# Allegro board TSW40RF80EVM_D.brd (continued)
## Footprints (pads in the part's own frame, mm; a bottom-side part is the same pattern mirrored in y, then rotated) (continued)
CON_THVT_USBMINI_AB_F
  round 1.321 hole 0.813: 1(-1.6,-1.295) 2(-0.813,1.295) 3(0,-1.295) 4(0.787,1.295) 5(1.6,-1.295)
  oval 1.651x3.988 hole 0.889x2.642: MT1(-3.645,0) MT2(3.645,0)
DBV5
  rect 1.4x0.5 smd: 1(-1.1,0.95) 2(-1.1,0) 3(-1.1,-0.95) 4(1.1,-0.95) 5(1.1,0.95)
HDR_THVT_1X2_79_M
  rect 1.321x1.321 hole 0.813: 1(0,1)
  round 1.321 hole 0.813: 2(0,-1)
HDR_THVT_1X2_100_M
  rect 1.473x1.473 hole 0.965: 1(0,0)
  round 1.473 hole 0.965: 2(0,-2.54)
HDR_THVT_1X3_79_M
  rect 1.321x1.321 hole 0.813: 1(0,2)
  round 1.321 hole 0.813: 2(0,0) 3(0,-1.995)
HDR_THVT_2X5_79_M
  rect 1.321x1.321 hole 0.813: 1(-1,4)
  round 1.321 hole 0.813: 2(1,4) 3(-1,2) 4(1,2) 5(-1,0.005) 6(1,0.005) 7(-1,-1.995) 8(1,-1.995) 9(-1,-3.995) 10(1,-3.995)
HEATSINK_350X700
  rect 5.791x5.791 smd: 1(-5.715,-1.27) 2(5.715,1.27)
HEATSINK_SVT_10-1003850
  round 5.715 hole 3.175: MTG1(-3.175,18.415) MTG2(1.27,-19.685)
IND_SM_110X138
  rect 1.524x3.2 smd: 1(-1.206,0) 2(1.156,0)
IND_SM_142X189
  rect 2.007x3.505 smd: 1(-1.613,0) 2(1.613,0)
JACK_THVT_3_520X343X421
  oval 2.032x4.521 hole 1x3.5: 1(0,0)
  oval 4.013x2.032 hole 3x1: 2(-2.95,5.5) 3(-5.55,2.8)
LED_0603
  rect 0.762x0.813 smd: 1(-0.787,0) 2(0.787,0)
LED_1206
  rect 1.27x1.6 smd: 1(-1.524,0) 2(1.524,0)
LQFP_64_402X402_20
  round 1.016 smd: (-6.35,6.35) (6.35,-6.35)
  rect 2.032x0.33 smd: 1(-5.625,3.75) 2(-5.625,3.25) 3(-5.625,2.75) 4(-5.625,2.25) 5(-5.625,1.75) 6(-5.625,1.25) 7(-5.625,0.75) 8(-5.625,0.25) 9(-5.625,-0.25) 10(-5.625,-0.75) 11(-5.625,-1.25) 12(-5.625,-1.75) 13(-5.625,-2.25) 14(-5.625,-2.75) 15(-5.625,-3.25) 16(-5.625,-3.75) 33(5.625,-3.75) 34(5.625,-3.25) 35(5.625,-2.75) 36(5.625,-2.25) 37(5.625,-1.75) 38(5.625,-1.25) 39(5.625,-0.75) 40(5.625,-0.25) 41(5.625,0.25) 42(5.625,0.75) 43(5.625,1.25) 44(5.625,1.75) 45(5.625,2.25) 46(5.625,2.75) 47(5.625,3.25) 48(5.625,3.75)
  rect 0.33x2.032 smd: 17(-3.75,-5.625) 18(-3.25,-5.625) 19(-2.75,-5.625) 20(-2.25,-5.625) 21(-1.75,-5.625) 22(-1.25,-5.625) 23(-0.75,-5.625) 24(-0.25,-5.625) 25(0.25,-5.625) 26(0.75,-5.625) 27(1.25,-5.625) 28(1.75,-5.625) 29(2.25,-5.625) 30(2.75,-5.625) 31(3.25,-5.625) 32(3.75,-5.625) 49(3.75,5.625) 50(3.25,5.625) 51(2.75,5.625) 52(2.25,5.625) 53(1.75,5.625) 54(1.25,5.625) 55(0.75,5.625) 56(0.25,5.625) 57(-0.25,5.625) 58(-0.75,5.625) 59(-1.25,5.625) 60(-1.75,5.625) 61(-2.25,5.625) 62(-2.75,5.625) 63(-3.25,5.625) 64(-3.75,5.625)
MFG125_PLATED
  round 3.556 hole 3.175: 1(0,0)
MSOP_8_118X118_26
  rect 1.575x0.406 smd: 1(-2.225,0.975) 2(-2.225,0.325) 3(-2.225,-0.325) 4(-2.225,-0.975) 5(2.225,-0.975) 6(2.225,-0.325) 7(2.225,0.325) 8(2.225,0.975)
PDFN_6_P35MM
  custom 0.045x0.045 smd: 1(-0.5,0.35) 2(-0.5,0) 3(-0.5,-0.35) 4(0.5,-0.35) 5(0.5,0) 6(0.5,0.35)
PROBE_POINT_22PAD
  round 0.508 smd: 1(0,0)
PROBE_POINT_30PAD
  round 0.762 smd: 1(0,0)
QFN20_RGR_P5MM
  custom 0.076x0.076 smd: 1(-1.85,1) 2(-1.85,0.5) 3(-1.85,0) 4(-1.85,-0.5) 5(-1.85,-1) 6(-1,-1.85) 7(-0.5,-1.85) 8(0,-1.85) 9(0.5,-1.85) 10(1,-1.85) 11(1.85,-1) 12(1.85,-0.5) 13(1.85,0) 14(1.85,0.5) 15(1.85,1) 16(1,1.85) 17(0.5,1.85) 18(0,1.85) 19(-0.5,1.85) 20(-1,1.85)
  rect 2.032x2.032 smd: 21(0,0)
QFN40_RTA_RTB_RHA
  custom 0.076x0.076 smd: 1(-3.025,2.25) 2(-3.025,1.75) 3(-3.025,1.25) 4(-3.025,0.75) 5(-3.025,0.25) 6(-3.025,-0.25) 7(-3.025,-0.75) 8(-3.025,-1.25) 9(-3.025,-1.75) 10(-3.025,-2.25) 11(-2.25,-3.025) 12(-1.75,-3.025) 13(-1.25,-3.025) 14(-0.75,-3.025) 15(-0.25,-3.025) 16(0.25,-3.025) 17(0.75,-3.025) 18(1.25,-3.025) 19(1.75,-3.025) 20(2.25,-3.025) 21(3.025,-2.25) 22(3.025,-1.75) 23(3.025,-1.25) 24(3.025,-0.75) 25(3.025,-0.25) 26(3.025,0.25) 27(3.025,0.75) 28(3.025,1.25) 29(3.025,1.75) 30(3.025,2.25) 31(2.25,3.025) 32(1.75,3.025) 33(1.25,3.025) 34(0.75,3.025) 35(0.25,3.025) 36(-0.25,3.025) 37(-0.75,3.025) 38(-1.25,3.025) 39(-1.75,3.025) 40(-2.25,3.025)
  rect 4.572x4.572 smd: 41(0,0)
QFN_20_183X144_RGY
  rect 0.762x0.356 smd: 1(-2.125,-0.75) 10(2.125,-0.75) 11(2.125,0.75) 20(-2.125,0.75)
  rect 0.356x0.762 smd: 2(-1.75,-1.625) 3(-1.25,-1.625) 4(-0.75,-1.625) 5(-0.25,-1.625) 6(0.25,-1.625) 7(0.75,-1.625) 8(1.25,-1.625) 9(1.75,-1.625) 12(1.75,1.625) 13(1.25,1.625) 14(0.75,1.625) 15(0.25,1.625) 16(-0.25,1.625) 17(-0.75,1.625) 18(-1.25,1.625) 19(-1.75,1.625)
  rect 3.15x2.159 smd: 21(0,0)
QFN_20_199X199_0P65MM
  rect 0.991x0.356 smd: 1(-2.4,1.3) 2(-2.4,0.65) 3(-2.4,0) 4(-2.4,-0.65) 5(-2.4,-1.3) 11(2.4,-1.3) 12(2.4,-0.65) 13(2.4,0) 14(2.4,0.65) 15(2.4,1.3)
  rect 0.356x0.991 smd: 6(-1.3,-2.4) 7(-0.65,-2.4) 8(0,-2.4) 9(0.65,-2.4) 10(1.3,-2.4) 16(1.3,2.4) 17(0.65,2.4) 18(0,2.4) 19(-0.65,2.4) 20(-1.3,2.4)
  rect 3.15x3.15 smd: 21(0,0)
QFN_64_360X360_0P50MM_PWRPAD
  oval 1.016x0.305 smd: 1(-4.58,3.753) 2(-4.58,3.252) 3(-4.58,2.752) 4(-4.58,2.252) 5(-4.58,1.751) 6(-4.58,1.251) 7(-4.58,0.751) 8(-4.58,0.25) 9(-4.58,-0.25) 10(-4.58,-0.751) 11(-4.58,-1.251) 12(-4.58,-1.751) 13(-4.58,-2.252) 14(-4.58,-2.752) 15(-4.58,-3.252) 16(-4.58,-3.753) 33(4.58,-3.753) 34(4.58,-3.252) 35(4.58,-2.752) 36(4.58,-2.252) 37(4.58,-1.751) 38(4.58,-1.251) 39(4.58,-0.751) 40(4.58,-0.25) 41(4.58,0.25) 42(4.58,0.751) 43(4.58,1.251) 44(4.58,1.751) 45(4.58,2.252) 46(4.58,2.752) 47(4.58,3.252) 48(4.58,3.753)
  oval 0.305x1.016 smd: 17(-3.753,-4.58) 18(-3.252,-4.58) 19(-2.752,-4.58) 20(-2.252,-4.58) 21(-1.751,-4.58) 22(-1.251,-4.58) 23(-0.751,-4.58) 24(-0.25,-4.58) 25(0.25,-4.58) 26(0.751,-4.58) 27(1.251,-4.58) 28(1.751,-4.58) 29(2.252,-4.58) 30(2.752,-4.58) 31(3.252,-4.58) 32(3.753,-4.58) 49(3.753,4.58) 50(3.252,4.58) 51(2.752,4.58) 52(2.252,4.58) 53(1.751,4.58) 54(1.251,4.58) 55(0.751,4.58) 56(0.25,4.58) 57(-0.25,4.58) 58(-0.751,4.58) 59(-1.251,4.58) 60(-1.751,4.58) 61(-2.252,4.58) 62(-2.752,4.58) 63(-3.252,4.58) 64(-3.753,4.58)
  rect 7.366x7.366 smd: 65(0,0)
QFN_72_10MMX10MM_0P50MM_PWRPAD
  oval 0.6x0.24 smd: 1(-4.9,4.25) 2(-4.9,3.75) 3(-4.9,3.25) 4(-4.9,2.75) 5(-4.9,2.25) 6(-4.9,1.75) 7(-4.9,1.25) 8(-4.9,0.75) 9(-4.9,0.25) 10(-4.9,-0.25) 11(-4.9,-0.75) 12(-4.9,-1.25) 13(-4.9,-1.75) 14(-4.9,-2.25) 15(-4.9,-2.75) 16(-4.9,-3.25) 17(-4.9,-3.75) 18(-4.9,-4.25) 37(4.9,-4.25) 38(4.9,-3.75) 39(4.9,-3.25) 40(4.9,-2.75) 41(4.9,-2.25) 42(4.9,-1.75) 43(4.9,-1.25) 44(4.9,-0.75) 45(4.9,-0.25) 46(4.9,0.25) 47(4.9,0.75) 48(4.9,1.25) 49(4.9,1.75) 50(4.9,2.25) 51(4.9,2.75) 52(4.9,3.25) 53(4.9,3.75) 54(4.9,4.25)
  oval 0.24x0.6 smd: 19(-4.25,-4.9) 20(-3.75,-4.9) 21(-3.25,-4.9) 22(-2.75,-4.9) 23(-2.25,-4.9) 24(-1.75,-4.9) 25(-1.25,-4.9) 26(-0.75,-4.9) 27(-0.25,-4.9) 28(0.25,-4.9) 29(0.75,-4.9) 30(1.25,-4.9) 31(1.75,-4.9) 32(2.25,-4.9) 33(2.75,-4.9) 34(3.25,-4.9) 35(3.75,-4.9) 36(4.25,-4.9) 55(4.25,4.9) 56(3.75,4.9) 57(3.25,4.9) 58(2.75,4.9) 59(2.25,4.9) 60(1.75,4.9) 61(1.25,4.9) 62(0.75,4.9) 63(0.25,4.9) 64(-0.25,4.9) 65(-0.75,4.9) 66(-1.25,4.9) 67(-1.75,4.9) 68(-2.25,4.9) 69(-2.75,4.9) 70(-3.25,4.9) 71(-3.75,4.9) 72(-4.25,4.9)
  rect 8.382x8.382 smd: 73(0,0)
SMA_SMEL_DUAL_PSF-S01_250X215
  rect 0.508x4.064 smd: 1(0,-2.032)
  rect 3.048x4.064 smd: 2(-3.556,-2.032) 3(3.556,-2.032) 4(-3.556,-2.032) 5(3.556,-2.032)
SMA_THVT_312X312
  round 2.337 hole 1.575: 1(0,0)
  round 2.464 hole 1.702: 2(-2.54,2.54) 3(2.54,2.54) 4(2.54,-2.54) 5(-2.54,-2.54)
SMP_B120
  rect 0.508x1.321 smd: 1(0,-3.1)
  custom 1.3x1.3 smd: 2(0,0)
SON_DSG_8
  rect 0.508x0.33 smd: 1(-0.903,0.75) 2(-0.903,0.25) 3(-0.903,-0.25) 4(-0.903,-0.75) 5(0.903,-0.75) 6(0.903,-0.25) 7(0.903,0.25) 8(0.903,0.75)
  rect 0.762x1.778 smd: 9(0,0)
SON_Q5B_8
  rect 1.372x0.711 smd: 1(-2.767,1.905) 2(-2.767,0.635) 3(-2.767,-0.635) 4(-2.767,-1.905) 5(2.767,-1.905) 6(2.767,-0.635) 7(2.767,0.635) 8(2.767,1.905)
SOT_416_3_63X31
  rect 0.508x0.356 smd: 1(0,-0.152) 2(0,-1.168) 3(1.295,-0.66)
SW_SMVT_SPST_EVQPJX_2
  rect 2.007x1.6 smd: 1(-2.7,0) 2(2.7,0)
TESTPOINT_62DIA
  round 2.337 hole 1.575: 1(0,0)
TFMR_5_150X150_50
  rect 1.651x0.762 smd: 1(1.587,1.27) 2(1.587,0) 3(1.587,-1.27) 4(-1.587,-1.27) 6(-1.587,1.27)
TP_THVT_060_RND
  round 1.575 hole 1.016: 1(0,0)
USIL_8_3MMX2P8MM_0P65MM
  rect 0.5x0.4 smd: 1(-1.1,0.975) 2(-1.1,0.325) 3(-1.1,-0.325) 4(-1.1,-0.975) 5(1.1,-0.975) 6(1.1,-0.325) 7(1.1,0.325) 8(1.1,0.975)
  rect 1.1x1.9 smd: 9(0,0)
VCXO_6_CUSTOM
  rect 5.74x1.956 smd: 1(-3.81,2.54) 2(-3.81,0) 3(-3.81,-2.54) 4(3.81,-2.54) 5(3.81,0) 6(3.81,2.54)
XTAL_4_SM_130X102
  rect 1.4x1.2 smd: 1(-1.1,-0.85) 2(1.1,-0.85) 3(1.1,0.85) 4(-1.1,0.85)

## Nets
1.8V_USB: C246.2 C250.2 C253.2 C262.1 C263.1 C265.2 C439.2 R327.1 U10.12(VCORE#12) U10.37(VCORE#37) U10.49(VREGOUT) U10.64(VCORE#64) U11.2(VCCA) U11.10(OE) U32.2(VCCA) U32.10(OE)
3.3V_USB: C245.2 C249.2 C251.2 C255.2 C259.1 C264.1 C268.2 C438.1 FB12.1 FB13.3 FB14.1 R155.2 R156.2 R157.2 R326.1 U10.20(VCCIO#20) U10.31(VCCIO#31) U10.42(VCCIO#42) U10.50(VREGIN) U10.56(VCCIO#56) U11.19(VCCB) U12.6(ORG) U12.8(VCC) U32.19(VCCB)
5.0V_SOURCE: F1.1 J17.1 Q4.5(D5) Q4.6(D6) Q4.7(D7) Q4.8(D8) TP10.1(TP) U14.5(VIN)
5VUSB: R138.2 R146.1
+1.8V_ANA: C71.1 C72.2 C73.1 C74.1 C75.1 C76.2 C77.1 C78.1 C302.1 C303.1 FB49.2 PP8.1 R363.2 U1.G11(VDDA18#G11) U1.G12(VDDOUT18#G12) U1.H11(VDDA18#H11) U1.H12(VDDOUT18#H12)
+1.8V_CLK: C79.1 C80.2 C81.1 C82.1 C101.1 C102.2 C103.1 C297.1 C298.1 FB47.2 PP5.1 U1.B7(VDDTX18) U1.B9(VDDAPLL18#B9) U1.B10(VDDAPLL18#B10)
+1.8V_DIG: C89.1 C90.2 C91.1 C92.1 C93.1 C94.2 C96.1 C97.1 C98.2 C99.1 C100.1 C300.1 C301.1 FB48.2 JP1.1(PIN1) JP2.1(PIN1) PP7.1 R30.1 U1.B3(VDDS18#B3) U1.B4(VDDS18#B4) U1.H2(VDDR18#H2) U1.H5(VDDIO18) U1.J2(VDDR18#J2)
+1.8V_VDDVCO: C83.1 C84.2 C85.1 C86.1 C443.1 C444.1 L17.1 PP52.1 U1.D9(VDDAVCO18#D9) U1.E9(VDDAVCO18#E9)
+3.3V: C426.2 FB38.1 FB39.1 R219.1 R225.1 U23.8(VOUT)
+3.3V_LMX: C172.1 C173.1 C174.2 C176.1 C179.1 C180.2 C185.1 C187.2 C353.1 C354.1 C355.1 C356.1 FB38.2 PP23.1 R60.2 U5.7(VCCDIG) U5.11(VCCCP) U5.15(VCCDIV) U5.21(VCCBUF) U5.26(VCCDBLR) U5.37(VCCVCO)
+3.3V_LMXRF: C139.1 C168.1 C178.1 C358.1 C359.1 C423.1 C424.1 FB39.2 R38.1 R39.1 R58.2 R59.2 R61.2 R62.2 R213.1 R214.1 R215.1 R216.1
+3.3VCLK: C346.1 C347.1 FB2.1 FB3.1 FB4.1 FB5.1 FB6.1 FB10.1 FB11.1 FB37.3 JP6.2 PP22.1 R73.1 R104.1 R112.1 R359.1 U22.3(SENSE)
+5VIN: C252.1 C275.1 C276.1 C277.2 C327.2 D6.1(ANODE) D7.1(ANODE) FB16.1 FB21.1 FB22.1 FB23.1 J38.1 L13.1 L15.1 L16.1 R136.2 U8.1(VIN) U21.12(BIAS)
+5VIN_ADC: C435.1 C436.2 C437.1 FB25.1 FB26.1 FB27.1 FB44.1 L10.1 L11.1 L12.1 R332.1
+5VIN_CLK: C340.1 C341.2 C342.2 C425.1 C440.1 C441.2 C442.1 FB45.1 R340.2 R342.2 U22.15(IN2) U22.16(IN1) U23.3(VIN1) U23.4(VIN2)
-1.8V: C279.1 FB17.1 U15.4(VOUT)
-1.8V_VEE: C104.1 C105.2 C106.1 C107.1 C108.1 C109.1 C278.1 C280.1 PP1.1 R161.2 R236.1 U1.D10(VEEB_-1.8V#D10) U1.E10(VEEB_-1.8V#E10) U1.K10(VEEA_-1.8V#K10) U1.L10(VEEA_-1.8V#L10)
AVDD1.9V: C142.1 C143.1 C144.1 C145.1 C146.1 C147.1 C362.1 C364.1 PP31.1 R356.1 U2.10(AVDD19#10) U2.16(AVDD19#16) U2.24(AVDD19#24) U2.31(AVDD19#31) U2.39(AVDD19#39) U2.45(AVDD19#45)
AVDD1.15V: C112.1 C113.1 C114.1 C115.1 C116.1 C117.1 C118.1 C119.1 C120.1 C121.1 C122.1 C381.1 C382.1 PP32.1 R357.1 U2.9(AVDD#9) U2.12(AVDD#12) U2.15(AVDD#15) U2.17(AVDD#17) U2.25(AVDD#25) U2.30(AVDD#30) U2.38(AVDD#38) U2.40(AVDD#40) U2.43(AVDD#43) U2.44(AVDD#44) U2.46(AVDD#46)
DVDD1.15V: C128.1 C129.1 C130.1 C131.1 C132.1 C133.1 C134.1 C261.1 C377.1 C378.1 JP4.1(PIN1) PP33.1 R47.2 R358.1 U2.4(DVDD#4) U2.8(DVDD#8) U2.47(DVDD#47) U2.51(DVDD#51) U2.57(DVDD#57) U2.64(DVDD#64) U2.70(DVDD#70) U31.2(VCCA) U31.10(OE)
DVDD_1P0V: C30.1 C31.2 C32.1 C33.1 C34.1 C35.1 C36.1 C37.1 C38.1 C39.1 C40.1 C41.1 C42.1 C288.1 C289.1 PP3.1 R168.2 R237.1 R360.2 U1.A5(VDD_1V#A5) U1.B5(VDD_1V#B5) U1.C5(VDD_1V#C5) U1.D5(VDD_1V#D5) U1.D7(VDD_1V#D7) U1.E3(VDD_1V#E3) U1.E4(VDD_1V#E4) U1.E5(VDD_1V#E5) U1.E6(VDD_1V#E6) U1.F4(VDD_1V#F4) U1.F5(VDD_1V#F5) U1.G4(VDD_1V#G4) U1.G5(VDD_1V#G5)
GND: C28.2 C29.2 C30.2 C31.1 C32.2 C33.2 C34.2 C35.2 C36.2 C37.2 C38.2 C39.2 C40.2 C41.2 C42.2 C43.2 C44.1 C45.2 C46.2 C47.2 C48.1 C49.2 C50.2 C51.2 C52.1 C53.2 C54.2 C55.2 C56.1 C57.2 C58.2 C59.2 C60.1 C61.2 C62.2 C63.2 C64.1 C65.2 C66.2 C67.2 C68.1 C69.2 C70.2 C71.2 C72.1 C73.2 C74.2 C75.2 C76.1 C77.2 C78.2 C79.2 C80.1 C81.2 C82.2 C83.2 C84.1 C85.2 C86.2 C87.1 C88.2 C89.2 C90.1 C91.2 C92.2 C93.2 C94.1 C95.2 C96.2 C97.2 C98.1 C99.2 C100.2 C101.2 C102.1 C103.2 C104.2 C105.1 C106.2 C107.2 C108.2 C109.2 C112.2 C113.2 C114.2 C115.2 C116.2 C117.2 C118.2 C119.2 C120.2 C121.2 C122.2 C128.2 C129.2 C130.2 C131.2 C132.2 C133.2 C134.2 C139.2 C142.2 C143.2 C144.2 C145.2 C146.2 C147.2 C154.2 C157.2 C159.1 C161.1 C165.1 C166.1 C168.2 C172.2 C173.2 C174.1 C176.2 C177.1 C178.2 C179.2 C180.1 C182.2 C183.1 C185.2 C186.1 C187.1 C188.1 C189.1 C190.1 C191.1 C192.2 C194.2 C195.2 C200.2 C203.2 C206.1 C218.1 C219.1 C222.1 C223.1 C225.1 C229.1 C232.1 C233.1 C234.1 C235.1 C236.1 C237.1 C238.1 C239.1 C240.1 C241.2 C242.2 C243.1 C244.1 C245.1 C246.1 C247.2 C248.2 C249.1 C250.1 C251.1 C252.2 C253.1 C254.2 C255.1 C256.2 C257.2 C258.2 C259.2 C260.1 C261.2 C262.2 C263.2 C264.2 C265.1 C266.2 C267.2 C268.1 C269.2 C270.2 C273.2 C274.1 C275.2 C276.2 C277.1 C278.2 C279.2 C280.2 C281.2 C283.2 C285.2 C288.2 C289.2 C290.1 C294.1 C295.2 C297.2 C298.2 C299.2 C300.2 C301.2 C302.2 C303.2 C308.2 C309.2 C313.1 C314.2 C315.2 C316.2 C318.2 C320.2 C324.2 C325.2 C326.1 C327.1 C340.2 C341.1 C342.1 C343.2 C344.2 C345.2 C346.2 C347.2 C348.2 C353.2 C354.2 C355.2 C356.2 C358.2 C359.2 C362.2 C364.2 C365.2 C366.1 C367.2 C376.1 C377.2 C378.2 C379.2 C380.1 C381.2 C382.2 C423.2 C424.2 C425.2 C426.1 C435.2 C436.1 C437.2 C438.2 C439.1 C440.2 C441.1 C442.2 C443.2 C444.2 C445.1 C446.1 C447.1 C448.1 D1.2(CATHODE) D2.2(CATHODE) D3.2(CATHODE) D4.2(CATHODE) D5.2(CATHODE) D9.2(CATHODE) D10.2(CATHODE) FB13.2 FB17.2 FB18.2 FB20.2 FB37.2 FB40.2 FB41.2 FB42.2 FB53.2 HS1.MTG1 HS1.MTG2 HS2.1 HS2.2 J1.2(GND#2) J1.3(GND#3) J1.4(GND#4) J1.5(GND#5) J3.2(GND#2) J3.3(GND#3) J3.4(GND#4) J3.5(GND#5) J4.2(GND#2) J4.3(GND#3) J4.4(GND#4) J4.5(GND#5) J8.2(SHIELD1) J9.2(SHIELD2) J9.3(SHIELD3) J9.4(SHIELD4) J9.5(SHIELD1) J10.2(SHIELD2) J10.3(SHIELD3) J10.4(SHIELD4) J10.5(SHIELD1) J12.2(GND#2) J12.3(GND#3) J12.4(GND#4) J12.5(GND#5) J13.2(SHIELD1) J14.A1 J14.A4 J14.A5 J14.A8 J14.A9 J14.A12 J14.A13 J14.A16 J14.A17 J14.A20 J14.A21 J14.A24 J14.A25 J14.A28 J14.A29 J14.A32 J14.A33 J14.A36 J14.A37 J14.A40 J14.B2 J14.B3 J14.B6 J14.B7 J14.B10 J14.B11 J14.B14 J14.B15 J14.B18 J14.B19 J14.B22 J14.B23 J14.B26 J14.B27 J14.B30 J14.B31 J14.B34 J14.B35 J14.B38 J14.B39 J14.C1 J14.C4 J14.C5 J14.C8 J14.C9 J14.C12 J14.C13 J14.C16 J14.C17 J14.C20 J14.C21 J14.C24 J14.C25 J14.C28 J14.C29 J14.C32 J14.C33 J14.C36 J14.C38 J14.C40 J14.D2 J14.D3 J14.D6 J14.D7 J14.D10 J14.D13 J14.D16 J14.D19 J14.D22 J14.D25 J14.D28 J14.D37 J14.D39 J14.E1 J14.E4 J14.E5 J14.E8 J14.E11 J14.E14 J14.E17 J14.E20 J14.E23 J14.E26 J14.E29 J14.E32 J14.E35 J14.E38 J14.E40 J14.F3 J14.F6 J14.F9 J14.F12 J14.F15 J14.F18 J14.F21 J14.F24 J14.F27 J14.F30 J14.F33 J14.F36 J14.F39 J14.G1 J14.G4 J14.G5 J14.G8 J14.G11 J14.G14 J14.G17 J14.G20 J14.G23 J14.G26 J14.G29 J14.G32 J14.G35 J14.G38 J14.G40 J14.H3 J14.H6 J14.H9 J14.H12 J14.H15 J14.H18 J14.H21 J14.H24 J14.H27 J14.H30 J14.H33 J14.H36 J14.H39 J14.J1 J14.J4 J14.J5 J14.J8 J14.J11 J14.J14 J14.J17 J14.J20 J14.J23 J14.J26 J14.J29 J14.J32 J14.J35 J14.J38 J14.J40 J14.K2 J14.K3 J14.K6 J14.K9 J14.K12 J14.K15 J14.K18 J14.K21 J14.K24 J14.K27 J14.K30 J14.K33 J14.K36 J14.K39 J15.5(GND) J15.MT1(SHLD#MT1) J15.MT2(SHLD#MT2) J17.2 J17.3 J38.2 JP1.3(PIN3) JP2.3(PIN3) JP3.2(PIN2) JP4.3(PIN3) JP5.1 JP7.2(PIN2) JP8.2(PIN2) MT1.1 MT2.1 MT3.1 Q1.2(E) Q2.2(E) R2.2 R3.2 R21.2 R22.2 R24.2 R25.2 R31.2 R49.1 R50.1 R67.1 R70.2 R71.2 R72.2 R76.2 R77.2 R78.2 R79.2 R80.2 R81.1 R82.1 R87.2 R89.2 R90.2 R93.2 R94.2 R95.2 R100.2 R101.2 R102.2 R103.2 R105.2 R106.2 R108.2 R109.2 R110.2 R111.2 R114.2 R116.2 R117.2 R119.2 R120.2 R121.2 R122.1 R147.2 R151.1 R163.2 R169.2 R173.2 R182.1 R188.1 R189.1 R190.1 R200.2 R203.2 R206.2 R208.2 R210.2 R212.2 R218.2 R220.2 R239.2 R256.2 R331.1 R334.1 R335.1 R337.2 R339.2 R341.2 R343.2 R354.2 SW1.1 T3.4(PRI) TP1.1(TP) TP2.1(TP) TP6.1(TP) TP7.1(TP) TP8.1(TP) TP9.1(TP) TP11.1(TP) TP14.1(TP) U1.A2(DGND#A2) U1.A8(VSSCLK#A8) U1.A11(VSSCLK#A11) U1.B2(DGND#B2) U1.B8(VSSCLK#B8) U1.B11(VSSCLK#B11) U1.B12(VSSCLK#B12) U1.C2(DGND#C2) U1.C11(AGNDB#C11) U1.C12(AGNDB#C12) U1.D2(DGND#D2) U1.D6(DGND#D6) U1.D11(AGNDB#D11) U1.D12(VOUTBP) U1.E2(DGND#E2) U1.E7(DGND#E7) U1.E11(AGNDB#E11) U1.F2(DGND#F2) U1.F6(DGND#F6) U1.F8(VSSCLK#F8) U1.F9(VSSCLK#F9) U1.F10(VSSCLK#F10) U1.F12(AGNDB#F12) U1.G2(DGND#G2) U1.G7(DGND#G7) U1.H6(DGND#H6) U1.J7(DGND#J7) U1.J8(VSSCLK#J8) U1.J9(VSSCLK#J9) U1.J10(VSSCLK#J10) U1.J12(AGNDA#J12) U1.K2(DGND#K2) U1.K11(AGNDA#K11) U1.L2(DGND#L2) U1.L3(DGND#L3) U1.L4(DGND#L4) U1.L5(DGND#L5) U1.L11(AGNDA#L11) U1.L12(VOUTAP) U1.M6(DGND#M6) U1.M11(AGNDA#M11) U1.M12(AGNDA#M12) U2.3(DGND#3) U2.18(AGND#18) U2.23(AGND#23) U2.26(AGND#26) U2.29(AGND#29) U2.32(AGND#32) U2.37(AGND#37) U2.52(DGND#52) U2.60(DGND#60) U2.67(DGND#67) U2.73(THERMALPAD) U3.2(GND) U4.2(GND) U5.2(GND#2) U5.4(GND#4) U5.6(GND#6) U5.13(GND#13) U5.14(GND#14) U5.25(GND#25) U5.31(GND#31) U5.34(GND#34) U5.39(GND#39) U5.40(GND#40) U5.41(PWRPAD) U7.65(DAP) U8.2(GND) U10.1(GND#1) U10.5(GND#5) U10.10(AGND) U10.11(GND#11) U10.13(TEST) U10.15(GND#15) U10.25(GND#25) U10.35(GND#35) U10.47(GND#47) U10.51(GND#51) U11.11(GND) U11.21(PWRPAD) U12.5(GND) U14.2(GND) U15.2(GND) U15.9(PAD) U17.5(GND#5) U17.6(GND#6) U17.9(PWRPAD) U19.5(GND#5) U19.6(GND#6) U19.9(PWRPAD) U21.8(GND#8) U21.18(GND#18) U21.21(THERMPAD) U22.7(GND) U22.8(1P6V) U22.21(PWRPAD) U23.5(GND#5) U23.6(GND#6) U23.9(PWRPAD) U24.5(GND#5) U24.6(GND#6) U24.9(PWRPAD) U25.5(GND#5) U25.6(GND#6) U25.9(PWRPAD) U26.5(GND#5) U26.6(GND#6) U26.9(PWRPAD) U27.2(GND) U28.2(GND) U29.2(GND) U30.2(GND) U31.11(GND) U31.21(PWRPAD) U32.11(GND) U32.21(PWRPAD) Y1.3(GND) Y2.2 Y2.4
V1: JP3.1(PIN1) R38.2 U29.1(V1) U30.1(V1)
V2: JP3.3(PIN3) R39.2 U29.5(V2) U30.5(V2)
V3: JP7.1(PIN1) R214.2 U27.1(V1) U28.1(V1)
V4: JP7.3(PIN3) R213.2 U27.5(V2) U28.5(V2)
V5: JP8.1(PIN1) R216.2 U3.1(V1) U4.1(V1)
V6: JP8.3(PIN3) R215.2 U3.5(V2) U4.5(V2)
1P0V: FB50.1 FB51.1 FB52.1 R176.1
1P8V: C295.1 FB24.2 FB47.1 FB48.1 FB49.1 L14.2 L17.2 R238.1
3P3VAUX: J14.D32 PP51.1
+1P0V_ANA: C67.1 C68.2 C69.1 C70.1 C324.1 C325.1 FB52.2 PP15.1 R365.2 U1.F11(VDDAB_1V) U1.J11(VDDAA_1V)
+1P0V_CLK: C51.1 C52.2 C53.1 C54.1 C55.1 C56.2 C57.1 C58.1 C63.1 C64.2 C65.1 C66.1 C87.2 C88.1 C95.1 C308.1 C309.1 FB50.2 PP11.1 U1.B6(VDDTX) U1.D8(VDDPLL_1V#D8) U1.E8(VDDPLL_1V#E8) U1.G9(VDDCLK_1V#G9) U1.G10(VDDL2B_1V) U1.H9(VDDCLK_1V#H9) U1.H10(VDDL2A_1V)
+1P0V_DIG: C43.1 C44.2 C45.1 C46.1 C314.1 C316.1 FB51.2 PP13.1 R361.1 U1.F7(VDDE_1V#F7) U1.G6(VDDE_1V#G6) U1.H7(VDDE_1V#H7) U1.J6(VDDE_1V#J6)
+1P0V_VDDL1: C47.1 C48.2 C49.1 C50.1 C59.1 C60.2 C61.1 C62.1 R360.1 R361.2 U1.G8(VDDL1B_1V) U1.H3(VDDT_1V#H3) U1.H8(VDDL1A_1V) U1.J3(VDDT_1V#J3)
A_IN: C160.1 J9.1(CENTER)
ADC_CLK: C153.1 J8.1(CENTER)
ADC_CLKINM: C428.2 R229.1 U2.28(CLKINM)
ADC_CLKINP: C427.2 R229.2 U2.27(CLKINP)
ADC_LKXEN: C434.1 U28.6(RFC)
ADC_LKXEP: C433.1 U27.6(RFC)
ADC_LXEN: C432.1 U30.6(RFC)
ADC_LXEP: C431.1 U29.6(RFC)
ADC_RESET: R49.2 SW2.2 U2.48(RESET) U31.6(A5)
ADC_SCLK: U2.6(SCLK) U31.1(A1)
ADC_SDIO: U2.5(SDATA) U31.3(A2)
ADC_SDO: U2.11(SDOUT) U31.4(A3)
ADC_SEN: U2.7(SEN) U31.5(A4)
ADC_SYNC_N: J14.G13 U2.36(SYNCBM)
ADC_SYNC_P: J14.G12 U2.35(SYNCBP)
ADC_SYSREFN: R45.1 R99.2 R102.1 U2.34(SYSREFM)
ADC_SYSREFP: R45.2 R96.2 R103.1 U2.33(SYSREFP)
AIN+: C162.1 R55.2 T4.3(SEC) T5.1(SEC DOT)
AIN-: C158.1 R54.2 T4.1(SEC DOT) T5.3(SEC)
AINM: C158.2 T5.4(PRI) U2.41(INAM)
AINP: C162.2 T5.6(PRI DOT) U2.42(INAP)
ALARM: TP3.1(TP) U1.K8(ALARM)
ATEST: TP15.1(TP) U1.C8(ATEST)
B_IN: C164.1 J10.1(CENTER)
BIN+: C163.1 R56.2 T6.1(SEC DOT) T7.3(SEC)
BIN-: C167.1 R57.2 T6.3(SEC) T7.1(SEC DOT)
BINM: C167.2 T7.6(PRI DOT) U2.14(INBM)
BINP: C163.2 T7.4(PRI) U2.13(INBP)
CAR_SYSREF_M: R86.1 R89.1 U7.4(SDCLKOUT1N)
CAR_SYSREF_P: R85.1 R90.1 U7.3(SDCLKOUT1P)
CAR_SYSREFM: J14.G10 R86.2
CAR_SYSREFP: J14.G9 R85.2
CE: JP5.2 R60.1 U5.1(CE)
CLK_LAO_0M: J14.G7 R118.2
CLK_LAO_0P: J14.G6 R115.2
CLKIN0_N: C206.2 U7.38(CLKIN0N)
CLKIN0_P: C204.2 U7.37(CLKIN0P)
CLKIN1N: C384.2 R234.1 U7.35(CLKIN1N/FBCLKINN/FINN)
CLKIN1P: C383.2 R234.2 U7.34(CLKIN1P/FBCLKINP/FINP)
CLKLA_0M: R118.1 R119.1 U7.63(DCLKOUT12N)
CLKLA_0P: R115.1 R117.1 U7.62(DCLKOUT12P)
CP1: C198.1 C200.1 R73.2 U7.32(CPOUT1) Y1.1(VC)
CP2: C202.1 C203.1 U7.46(CPOUT2)
CPOUT: C192.1 C193.1 R68.1 U5.12(CPOUT)
DA0N: C111.2 J14.B13
DA0P: C110.2 J14.B12
DA1N: C124.2 J14.A15
DA1P: C123.2 J14.A14
DA2N: C126.2 J14.B17
DA2P: C125.2 J14.B16
DA3N: C135.2 J14.A19
DA3P: C127.2 J14.A18
DAC_ALT_SYNC_N: J14.F20 U1.C6(SYNC1BN)
DAC_ALT_SYNC_P: J14.F19 U1.C7(SYNC1BP)
DAC_CLKOUTN: C9.2 U4.4(RF2)
DAC_CLKOUTP: C7.2 U3.4(RF2)
DAC_RESET: C28.1 R30.2 R148.1 R329.2 SW1.2 U1.K9(RESETB)
DAC_SCLK: R232.1 R304.1 R309.1
DAC_SDENB: R231.1 R307.1 R311.1
DAC_SDIO: R230.1 R305.1 R310.1
DAC_SDO: R233.1 R306.1 R308.1
DAC_SYNC_N: J14.F11 U1.C3(SYNC0BN)
DAC_SYNC_P: J14.F10 U1.C4(SYNC0BP)
DACCLK_IN: C1.1 J1.1(CENTER)
DACCLK_N: C361.1 U1.A9(DACCLKN)
DACCLK_P: C360.1 U1.A10(DACCLKP)
DACCLK_SE: C1.2 R1.2 R2.1
DACCLKSE: R1.1 R3.1 U1.A12(DACCLKSE)
DB0N: C137.2 J14.A11
DB0P: C136.2 J14.A10
DB1N: C140.2 J14.C7
DB1P: C138.2 J14.C6
DB2N: C148.2 J14.A7
DB2P: C141.2 J14.A6
DB3N: C150.2 J14.A3
DB3P: C149.2 J14.A2
DCLKOUT2N: C197.1 R72.1 U7.16(DCLKOUT2N)
DCLKOUT2P: C196.1 R71.1 U7.15(DCLKOUT2P)
DCLKOUT4N: C208.1 R95.1 U7.25(DCLKOUT4N)
DCLKOUT4P: C207.1 R94.1 U7.24(DCLKOUT4P)
DM: J15.2(D-) R139.1
DP: J15.3(D+) R142.1
DP0_C2M_N: C18.1 J14.C3
DP0_C2M_P: C19.1 J14.C2
DP1_C2M_N: C22.1 J14.A23
DP1_C2M_P: C20.1 J14.A22
DP2_C2M_N: C23.1 J14.A27
DP2_C2M_P: C21.1 J14.A26
DP3_C2M_N: C24.1 J14.A31
DP3_C2M_P: C25.1 J14.A30
DP4_C2M_N: C15.1 J14.A35
DP4_C2M_P: C14.1 J14.A34
DP5_C2M_N: C10.1 J14.A39
DP5_C2M_P: C11.1 J14.A38
DP6_C2M_N: C12.1 J14.B37
DP6_C2M_P: C13.1 J14.B36
DP7_C2M_N: C17.1 J14.B33
DP7_C2M_P: C16.1 J14.B32
EEDATA: R159.1 U10.61(EEDATA) U12.3(DI)
EXT_ADCCLKINM: C430.1 R84.2 T3.3(SEC)
EXT_ADCCLKINP: C429.1 R83.1 T3.1(SEC DOT)
EXTIO: C29.1 U1.C10(EXTIO)
FMC_ADC_RESET: J14.D15 R328.1
FMC_ADC_SCK: J14.C14 R319.1
FMC_ADC_SDIO: J14.C15 R316.1
FMC_ADC_SDO: J14.C18 R318.1
FMC_ADC_SEN: J14.D14 R317.1
FMC_CTRL1: J14.C26 R51.1
FMC_CTRL2: J14.C27 R53.1
FMC_DAC_RESET: J14.E19 R329.1
FMC_DAC_SCK: J14.G16 R309.2
FMC_DAC_SDENB: J14.H16 R311.2
FMC_DAC_SDIO: J14.G15 R310.2
FMC_DAC_SDO: J14.H17 R308.2
FMC_LMK_CSB: J14.E10 U32.1(A1)
FMC_LMK_SCK: J14.E6 U32.5(A4)
FMC_LMK_SDIO: J14.E7 U32.4(A3)
FMC_LMK_SDO: J14.E9 U32.3(A2)
FMC_LMX_CSB: J14.E16 U32.6(A5)
FMC_LMX_SCK: J14.E12 U32.9(A8)
FMC_LMX_SDIO: J14.E13 U32.8(A7)
FMC_LMX_SDO: J14.E15 U32.7(A6)
FPGA_CLK1_N: C217.2 J14.K5
FPGA_CLK1_P: C216.2 J14.K4
FPGA_CLK1N: C217.1 R106.1 U7.52(DCLKOUT8N)
FPGA_CLK1P: C216.1 R105.1 U7.51(DCLKOUT8P)
FPGA_CLK2_N: C226.2 J14.J3
FPGA_CLK2_P: C224.2 J14.J2
FPGA_CLK2N: C226.1 R110.1 U7.50(SDCLKOUT9N)
FPGA_CLK2P: C224.1 R111.1 U7.49(SDCLKOUT9P)
FTDI_TCK: J5.2 U11.1(A1)
FTDI_TDI: J5.4 U11.3(A2)
FTDI_TDO: J5.6 U11.4(A3)
FTDI_TMS: J5.8 U11.5(A4)
FTDI_TRSTB: J5.10 R145.1
GA0: J14.C34 PP36.1
GA1: J14.D35 PP37.1
GPIO1: PP28.1 U2.19(GPIO1)
GPIO2: PP27.1 U2.63(GPIO2)
GTX_CLKM: C201.2 J14.D5
GTX_CLKP: C199.2 J14.D4
GTXCLKM: C201.1 R77.1 U7.2(DCLKOUT0N)
GTXCLKP: C199.1 R78.1 U7.1(DCLKOUT0P)
IOUTA: J3.1(CENTER) R20.1 R22.1
IOUTAM: C26.1 U1.K12(VOUTAM)
IOUTB: J4.1(CENTER) R23.1 R25.1
IOUTBP: C27.1 U1.E12(VOUTBM)
LMK LOCKED: D4.1(ANODE) R126.1
LMK-CSB: R295.2 U32.20(B1)
LMK-SCK: R292.2 U32.16(B4)
LMK-SDIO: R293.2 U32.17(B3)
LMK-SDO: R294.2 U32.18(B2)
LMK_ADC_CLKN: C448.2 L19.2 U28.4(RF2)
LMK_ADC_CLKP: C447.2 L18.2 U27.4(RF2)
LMK_CLKIN: C204.1 J12.1(CENTER) R93.1
LMK_CSB: R251.1 R295.1 U7.18(\\C\S\)
LMK_DAC_CLKN: C197.2 C361.2
LMK_DAC_CLKP: C196.2 C360.2
LMK_DAC_SYSREFN: R17.1 R74.2 R81.2
LMK_DAC_SYSREFP: R16.1 R75.2 R82.2
LMK_SCK: R248.1 R292.1 U7.19(SCK)
LMK_SDIO: R249.1 R293.1 U7.20(SDIO)
LMK_SDO: R122.2 R250.1 R294.1 U7.5(RESET)
LMX-CSB: R303.2 U32.15(B5)
LMX-SCLK: R300.2 U32.12(B8)
LMX-SDI: R302.2 U32.13(B7)
LMX-SDO: R301.2 U32.14(B6)
LMX_CLKAN: C171.2 U30.3(RF1)
LMX_CLKAP: C170.2 U29.3(RF1)
LMX_CLKBN: C184.2 C383.1
LMX_CLKBP: C181.2 C384.1
LMX_CSB: R298.1 R303.1 U5.24(CSB)
LMX_OSCM: C230.2 U5.9(OSCINM)
LMX_OSCP: C231.2 U5.8(OSCINP)
LMX_SCLK: R296.1 R300.1 U5.16(SCK)
LMX_SDI: R297.1 R302.1 U5.17(SDI)
LMX_SDO: R63.2 R299.1 R301.1
OSCI: C269.1 U10.2(OSCI) Y2.1
OSCINN: C228.2 C229.2 U7.44(OSCINN)
OSCINP: C221.2 C223.2 U7.43(OSCINP)
OSCN: C227.2 C228.1 R112.2 R116.1
OSCO: C270.1 U10.3(OSCO) Y2.3
OSCOUTN: C231.1 R121.1 U7.41(OSCOUTN)
OSCOUTP: C230.1 R120.1 U7.40(OSCOUTP)
OSCP: C220.2 C221.1 R104.2 R109.1
PDN: JP4.2(PIN2) U2.50(PDN)
PG_C2M: J14.D1 PP49.1
PG_M2C: J14.F1 PP48.1
PLL2 LOCKED: D5.1(ANODE) R127.1
PRSNT_M2C_L: J14.H2 PP47.1
RES0: J14.B40 PP50.1
RX0N: C18.2 U1.M4(RXN3)
RX0P: C19.2 U1.M5(RXP3)
RX1N: C22.2 U1.M3(RXN2)
RX1P: C20.2 U1.M2(RXP2)
RX2N: C23.2 U1.L1(RXN1)
RX2P: C21.2 U1.M1(RXP1)
RX3N: C24.2 U1.K1(RXN0)
RX3P: C25.2 U1.J1(RXP0)
RX4N: C15.2 U1.F1(RXN5)
RX4P: C14.2 U1.E1(RXP5)
RX5N: C10.2 U1.B1(RXN7)
RX5P: C11.2 U1.A1(RXP7)
RX6N: C12.2 U1.C1(RXN6)
RX6P: C13.2 U1.D1(RXP6)
RX7N: C17.2 U1.G1(RXN4)
RX7P: C16.2 U1.H1(RXP4)
SCAN_EN: R50.2 U2.49(SCAN_EN)
SCL: J14.C30 PP34.1
SCLK: R232.2 U1.L9(SCLK)
SDA: J14.C31 PP35.1
SDCLKOUT3N: R75.1 R80.1 U7.14(SDCLKOUT3N)
SDCLKOUT3P: R74.1 R79.1 U7.13(SDCLKOUT3P)
SDCLKOUT5N: R99.1 R101.1 U7.23(SDCLKOUT5N)
SDCLKOUT5P: R96.1 R100.1 U7.22(SDCLKOUT5P)
SDENB: R231.2 U1.M8(SDENB)
SDIO: R230.2 U1.M10(SDIO)
SDO: R233.2 U1.M9(SDO)
SLEEP: JP1.2(PIN2) U1.L8(SLEEP)
STAT 0: D2.1(ANODE) R124.1
STAT 1: D3.1(ANODE) R125.1
SYNC: R123.2 U7.6(SYNC)
SYSREF-N: R17.2 U1.A4(SYSREFN)
SYSREF-P: R16.2 U1.A3(SYSREFP)
TCK: J14.D29 PP44.1
TDI: J14.D30 PP43.1
TDO: J14.D31 PP45.1
TMS: J14.D33 PP46.1
TRST_L: J14.D34 PP42.1
TXA0_M: C111.1 U2.62(DA0M)
TXA0_P: C110.1 U2.61(DA0P)
TXA1_M: C124.1 U2.59(DA1M)
TXA1_P: C123.1 U2.58(DA1P)
TXA2_M: C126.1 U2.56(DA2M)
TXA2_P: C125.1 U2.55(DA2P)
TXA3_M: C135.1 U2.54(DA3M)
TXA3_P: C127.1 U2.53(DA3P)
TXB0_M: C137.1 U2.65(DB0M)
TXB0_P: C136.1 U2.66(DB0P)
TXB1_M: C140.1 U2.68(DB1M)
TXB1_P: C138.1 U2.69(DB1P)
TXB2_M: C148.1 U2.71(DB2M)
TXB2_P: C141.1 U2.72(DB2P)
TXB3_M: C150.1 U2.1(DB3M)
TXB3_P: C149.1 U2.2(DB3P)
TXENABLE: JP2.2(PIN2) U1.K6(TXENABLE)
USB_DM: C267.1 R139.2 U10.7(DM)
USB_DP: C266.1 R142.2 U10.8(DP)
USB_EECLK: R156.1 U10.62(EECLK) U12.2(CLK)
USB_EECS: R155.1 U10.63(EECS) U12.1(CS)
USB_REF: R147.1 U10.6(REF)
USB_RST: R150.2 U10.14(RESET)
VCM: C157.1 TP5.1(TP) U2.22(VCM)
VIO_B_M2C: J14.J39 J14.K40 PP41.1
VREF_A_M2C: J14.H1 PP38.1
VREF_B_M2C: J14.K1 PP39.1
Y2_N: R113.1 R114.1 Y1.4(OUT_N)
Y2_P: R107.1 R108.1 Y1.5(OUT_P)
YO2_N: C227.1 R113.2
YO2_P: C220.1 R107.2
N16791764: J15.1(VBUS) R138.1
N16791900: C257.1 C258.1 FB14.2 FB15.2 U10.4(VPHY)
N16791904: C247.1 C248.1 FB12.2 U10.9(VPLL)
N16792068: R146.2 R150.1 R151.2
N16792392: R157.1 R159.2 U12.4(DO)
N17033323: FB15.1 R137.1
N17033325: D9.1(ANODE) R137.2
N17828171: C254.1 C256.1 FB13.1 U8.5(VOUT)
N17829143: R136.1 U8.3(EN)
N17906763: J13.1(CENTER) R123.1
N18864728: Q2.1(B) R132.2
N18864763: J14.D17 R132.1
N18864775: J14.D18 R129.1
N18864798: Q2.3(C) R131.2
N18865554: D7.2(CATHODE) R131.1
N18967863: FB17.3 R236.2
N19080738: C218.2 C219.2 C222.2 C225.2 FB1.2 Y1.6(VDD)
N19081029: R359.2 Y1.2(NC)
N19083254: R126.2 U7.31(STATUS_LD1)
N19083268: R127.2 U7.48(STATUS_LD2)
N19083286: R125.2 U7.59(CLKIN_SEL1)
N19083328: R124.2 U7.58(CLKIN_SEL0)
N19083344: C241.1 U7.12(LDOBYP2)
N19083346: C242.1 U7.11(LDOBYP1)
N19083364: C232.2 C233.2 C234.2 FB2.2 U7.10(VCC1_VCO) U7.33(VCC5_DIG) U7.36(VCC6_PLL1)
N19083444: FB7.2 U7.39(VCC7_OSCOUT)
N19083446: FB9.2 U7.45(VCC9_CP2)
N19083508: C238.2 C239.2 C240.2 FB6.2 FB7.1 FB8.1 FB9.1 U7.47(VCC10_PLL2)
N19083566: C236.2 FB3.2 U7.21(VCC3_SYSREF)
N19083568: C235.2 FB5.2 U7.17(VCC2_CG1)
N19083616: C244.2 FB11.2 U7.64(VCC12_CG0)
N19083618: C243.2 FB10.2 U7.53(VCC11_CG3)
N19083707: C237.2 FB4.2 U7.26(VCC4_CG2)
N19234861: FB8.2 U7.42(VCC8_OSCIN)
N19402254: R251.2 U10.54(DDBUS3)
N19402263: R250.2 U10.53(DDBUS2)
N19402272: R249.2 U10.52(DDBUS1)
N19402281: R248.2 U10.48(DDBUS0)
N19909006: C290.2 FB18.1 U17.8(VOUT)
N20060120: C9.1 U1.A6(CLKTXN)
N20060672: C7.1 U1.A7(CLKTXP)
N20072726: C427.1 R228.2 U3.6(RFC)
N20072730: C428.1 R228.1 U4.6(RFC)
N20074990: C166.2 R57.1 T6.4(PRI)
N20074992: C164.2 C165.2 R56.1 T6.6(PRI DOT)
N20075215: C159.2 R54.1 T4.6(PRI DOT)
N20075219: C160.2 C161.2 R55.1 T4.4(PRI)
N20076572: D1.1(ANODE) R64.1
N20076618: C186.2 U5.29(VREFVCO#29)
N20076637: C188.2 U5.36(VREFVCO#36)
N20076686: C191.2 U5.33(VBIASVARAC)
N20076744: C170.1 R58.1 U5.23(RFOUTAP)
N20076746: C171.1 R59.1 U5.22(RFOUTAM)
N20076858: C177.2 U5.10(VCCIN)
N20076866: C181.1 R61.1 U5.18(RFOUTBP)
N20076868: C184.1 R62.1 U5.19(RFOUTBM)
N20076920: C193.2 R70.1
N20076959: C194.1 R68.2 R69.1
N20076978: C195.1 R69.2 U5.35(VTUNE)
N20077010: R67.2 U5.30(REXT)
N20077268: C182.1 C183.2 U5.27(VBIASBANK)
N20077503: R63.1 R64.2 U5.20(MUXOUT)
N20087628: R31.1 U1.C9(RBIAS)
N20088284: C27.2 R23.2 R24.1
N20088327: C26.2 R20.2 R21.1
N20098160: R312.2 U10.16(ADBUS0)
N20098174: C260.2 R326.2 R327.2 U31.19(VCCB)
N20098233: R313.2 U10.17(ADBUS1)
N20098235: R314.2 U10.18(ADBUS2)
N20098237: R315.2 U10.19(ADBUS3)
N20101383: R144.1 U11.16(B4)
N20101387: R143.1 U11.17(B3)
N20101391: R141.1 U11.18(B2)
N20101395: R140.1 U11.20(B1)
N20101461: U10.41(CDBUS3) U11.12(B8)
N20101463: U10.40(CDBUS2) U11.13(B7)
N20101465: U10.39(CDBUS1) U11.14(B6)
N20101467: U10.38(CDBUS0) U11.15(B5)
N20101487: R148.2 U10.32(BDBUS5)
N20101489: R145.2 U10.30(BDBUS4)
N20101501: R141.2 U10.27(BDBUS1)
N20101503: R144.2 U10.29(BDBUS3)
N20101505: R140.2 U10.26(BDBUS0)
N20101507: R143.2 U10.28(BDBUS2)
N20119510: C282.1 U15.7(C1-)
N20119513: C282.2 U15.8(C1+)
N20119835: C283.1 U15.3(CPOUT)
N20120157: R161.1 R163.1 U15.5(VFB)
N20121909: R168.1 R169.1 U17.7(FB)
N20122077: C285.1 FB22.2 L16.2 R338.2 U17.3(VIN1) U17.4(VIN2)
N20122091: R338.1 R339.1 U17.1(EN)
N20123661: C294.2 FB20.1 R362.2 U19.8(VOUT)
N20123671: C299.1 FB23.2 L13.2 R336.2 U19.3(VIN1) U19.4(VIN2)
N20123702: R171.1 R173.1 U19.7(FB)
N20123718: R336.1 R337.1 U19.1(EN)
N20123815: FB20.3 R238.2
N20149572: R297.2 U10.57(DDBUS5)
N20149573: R296.2 U10.55(DDBUS4)
N20149574: R299.2 U10.58(DDBUS6)
N20149575: R298.2 U10.59(DDBUS7)
N20165749: C207.2 C445.2 L18.1
N20165751: C208.2 C446.2 L19.1
N20264121: FB1.1 JP6.1
N20275378: FB42.3 R356.2
N20275382: C366.2 FB42.1 R199.1 U24.8(VOUT)
N20275455: C365.1 FB25.2 L10.2 U24.3(VIN1) U24.4(VIN2)
N20275475: R199.2 R200.1 U24.7(FB)
N20275808: C376.2 FB41.1 R202.1 U25.8(VOUT)
N20275812: C367.1 FB26.2 L11.2 R209.2 U25.3(VIN1) U25.4(VIN2)
N20275835: R202.2 R203.1 U25.7(FB)
N20276430: C380.2 FB40.1 R205.1 U26.8(VOUT)
N20276536: FB40.3 R358.2
N20276599: C379.1 FB27.2 L12.2 R211.2 U26.3(VIN1) U26.4(VIN2)
N20276622: R205.2 R206.1 U26.7(FB)
N20276940: FB41.3 R357.2
N20277804: R207.2 R332.2 U25.2(PG) U26.2(PG)
N20277812: R207.1 R208.1 U24.1(EN)
N20277928: R209.1 R210.1 U25.1(EN)
N20285160: C343.1 C344.1 C345.1 R224.2 U22.1(OUT1) U22.20(OUT2)
N20285162: C348.1 U22.14(NR)
N20285184: R342.1 R343.1 U22.13(EN)
N20285196: R188.2 U22.12(0P1V)
N20285198: R189.2 U22.11(0P2V)
N20285293: R190.2 U22.10(0P4V)
N20285833: C273.1 C274.2 F1.2 FB16.2 FB44.2 FB45.2 Q4.1(S1) Q4.2(S2) Q4.3(S3) R160.1
N20285975: Q4.4(G) U14.4(GATE)
N20288221: R211.1 R212.1 U26.1(EN)
N20326292: R304.2 U11.6(A5)
N20326294: R305.2 U11.7(A6)
N20326306: R306.2 U11.8(A7)
N20326308: R307.2 U11.9(A8)
N20413661: PP29.1 R51.2 R52.2 U2.20(CTRL1)
N20413665: PP30.1 R52.1 R53.2 U2.21(CTRL2)
N20414446: R47.1 SW2.1
N20417693: C153.2 T3.6(PRI DOT)
N20417714: C154.1 T3.2(NC)
N20426571: R217.1 R218.1 U15.6(EN)
N20426573: C281.1 FB21.2 L15.2 R217.2 U15.1(VIN)
N20442953: R219.2 R220.1 U23.7(FB)
N20484075: FB37.1 R224.1 R225.2
N20493705: R83.2 R84.1
N20497118: R330.2 U10.21(ADBUS4)
N20546375: C189.2 U5.38(VREGVCO)
N20546772: C190.2 U5.3(VBIASVCO)
N20549887: R171.2 R362.1 R363.1
N20556233: J5.1 U1.K4(TCLK)
N20556256: J5.3 U1.H4(TDI)
N20556281: J5.5 U1.J4(TDO)
N20556364: J5.7 U1.K5(TMS)
N20556495: J5.9 R239.1 U1.J5(TRSTB)
N20643618: C429.2 U29.4(RF2)
N20643644: C430.2 U30.4(RF2)
N20643698: C431.2 U27.3(RF1)
N20643721: C432.2 U28.3(RF1)
N20643769: C433.2 U3.3(RF1)
N20643792: C434.2 U4.3(RF1)
N20651473: D10.1(ANODE) R160.2
N20670192: R312.1 R319.2 U31.20(B1)
N20670214: R313.1 R316.2 U31.18(B2)
N20670236: R314.1 R318.2 U31.17(B3)
N20670258: R315.1 R317.2 U31.16(B4)
N20674238: Q1.1(B) R129.2
N20674280: D6.2(CATHODE) R128.1
N20698575: R328.2 R330.1 U31.15(B5)
N20715968: R331.2 U1.K3(TESTMODE)
N20730230: C318.1 C320.1 FB24.1 L14.1 R355.2 U21.15(IN1) U21.16(IN2) U21.17(IN3)
N20730282: R354.1 R355.1 U21.14(EN)
N20730294: C313.2 C315.1 C317.2 FB53.1 R364.1 U21.1(OUT1) U21.19(OUT2) U21.20(OUT3)
N20730354: C317.1 R254.2 R256.1 U21.3(FB)
N20730369: R334.2 U21.7(200MV)
N20730383: R335.2 U21.6(100MV)
N20730407: R182.2 U21.5(50MV)
N20730507: R180.2 U21.2(SNS)
N20730511: R180.1 R254.1 R364.2 R365.1
N20730545: C326.2 U21.13(NR/SS)
N20737136: R340.1 R341.1 U23.1(EN)
N20804074: FB18.3 R237.2
N20825969: FB53.3 R176.2
N176074941: C202.2 R87.1
N176076570: C198.2 R76.1
N206742472: Q1.3(C) R128.2

Pads without a net: J14 B1 B4 B5 B8 B9 B20 B21 B24 B25 B28 B29 C10 C11 C19 C22 C23 C35 C37 C39 D8 D9 D11 D12 D20 D21 D23 D24 D26 D27 D36 D38 D40 E2 E3 E18 E21 E22 E24 E25 E27 E28 E30 E31 E33 E34 E36 E37 E39 F2 F4 F5 F7 F8 F13 F14 F16 F17 F22 F23 F25 F26 F28 F29 F31 F32 F34 F35 F37 F38 F40 G2 G3 G18 G19 G21 G22 G24 G25 G27 G28 G30 G31 G33 G34 G36 G37 G39 H4 H5 H7 H8 H10 H11 H13 H14 H19 H20 H22 H23 H25 H26 H28 H29 H31 H32 H34 H35 H37 H38 H40 J6 J7 J9 J10 J12 J13 J15 J16 J18 J19 J21 J22 J24 J25 J27 J28 J30 J31 J33 J34 J36 J37 K7 K8 K10 K11 K13 K14 K16 K17 K19 K20 K22 K23 K25 K26 K28 K29 K31 K32 K34 K35 K37 K38; J15 4; T4 2; T5 2; T6 2; T7 2; U1 D3 D4 F3 G3 K7 L6 L7 M7; U5 5 28 32; U7 7 8 9 27 28 29 30 54 55 56 57 60 61; U8 4; U10 22 23 24 33 34 36 43 44 45 46 60; U12 7; U14 1 3; U17 2; U19 2; U21 4 9 10 11; U22 2 4 5 6 9 17 18 19; U23 2; U24 2; U31 7 8 9 12 13 14

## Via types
v1: diameter 0.457, hole 0.203, TOP to BOTTOM, 2575 vias
v2: diameter 0.559, hole 0.305, TOP to BOTTOM, 263 vias
v3: diameter 0.356, hole 0.152, TOP to BOTTOM, 1345 vias
v4: diameter 0.254, hole 0.127, TOP to BOTTOM, 2 vias
v5: diameter 0.508, hole 0.254, TOP to BOTTOM, 74 vias
v6: diameter 0.406, hole 0.203, TOP to BOTTOM, 44 vias
v7: diameter 0.762, hole 0.381, TOP to BOTTOM, 11 vias
v8: diameter 0.305, hole 0.152, TOP to BOTTOM, 12 vias

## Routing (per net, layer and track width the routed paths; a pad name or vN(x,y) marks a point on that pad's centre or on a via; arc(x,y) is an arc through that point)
1.8V_USB: length 6.1
  TOP w0.305: v3(86.61,45.31) 86.61,45.74 v3(86.61,45.74) ; C250.2 101.81,50.15 v3(101.78,50.19) ; 93.33,43.2 93.33,43.29 v3(93.7,43.66) ; 93.33,43.2 v3(93.73,42.8) ; 93.33,43.2 C263.1 92.75,43.2 v3(92.28,43.66) ; v3(85.32,41.66) v3(85.78,41.66) 85.78,41.66 C265.2 ; v3(102.82,43.66) 102.83,43.65 v3(103.64,43.65) ; C253.2 104.38,43.58 v3(104.47,43.66) ; C246.2 94.22,50.18 v3(94.23,50.19)
  L3_PWR_SIG w0.305: v3(104.47,43.66) 103.65,43.66 v3(103.64,43.65)
  BOTTOM w0.305: U11.2 85.32,41.66 v3(85.32,41.66)
  vias: v1(89.97,39.88) v3(85.52,51.31) v3(85.95,51.31) v3(86.61,47.65) v3(86.61,47.22) v3(92.99,43.66) v3(94.27,51.03) v3(101.78,51.87) v3(101.77,51.03)
3.3V_USB: length 1.2
  TOP w0.305: v3(88.76,41.66) 89.24,41.66 v3(89.24,41.66) ; v1(106.27,44.93) 106.09,45.11 FB12.1 106.01,45.15 v1(105.77,44.91)
  vias: v1(89.97,37.82) v1(90.47,47.24) v1(90.5,46.41) v1(97.99,41.37) v1(98.85,43.49) v1(98.86,42.65) v1(99.01,49.58) v1(100.15,43.5) v1(100.18,42.65) v1(100.69,52.49) v1(101.27,52.49) v1(105.94,47.55) v1(106.27,47.9) v1(109.7,52.3) v1(109.65,51.36) v1(109.68,50.47) v1(110.64,52.3) v1(110.64,51.33) v1(110.64,50.44) v3(88.8,51.31) v3(89.2,51.31) v3(91.54,46.15) v3(92.39,46.16) v3(93.24,46.14) v3(94.77,51.03) v3(94.76,50.18) v3(94.76,40.63) v3(94.77,39.78) v3(97.77,51.03) v3(97.76,50.21) v3(100.25,40.61) v3(100.25,39.47)
5.0V_SOURCE: length 263.3
  TOP w0.432: 130.3,3.68 J17.1 ; J17.1 135.69,2.24 ; J17.1 132.99,0.79 ; J17.1 130.3,2.24 ; J17.1 130.3,0.79 ; J17.1 135.69,0.79 ; J17.1 132.99,3.68 ; J17.1 135.69,3.68 ; 124.67,3.6 TP10.1 ; TP10.1 127.04,3.6 ; TP10.1 127.46,2.41 ; TP10.1 124.67,1.23 ; TP10.1 125.86,0.81 ; TP10.1 124.26,2.41 ; TP10.1 125.86,4.01 ; TP10.1 127.04,1.23
  TOP w0.508: v1(130.34,13.78) 130.34,10.59 v2(130.21,10.46)
  L3_PWR_SIG w0.432: 130.3,0.79 J17.1 ; J17.1 135.69,0.79 ; J17.1 132.99,3.68 ; J17.1 130.3,3.68 ; J17.1 132.99,0.79 ; J17.1 135.69,2.24 ; J17.1 130.3,2.24 ; J17.1 135.69,3.68 ; 124.67,3.6 TP10.1 ; TP10.1 124.26,2.41 ; TP10.1 127.04,1.23 ; TP10.1 125.86,4.01 ; TP10.1 127.04,3.6 ; TP10.1 124.67,1.23 ; TP10.1 125.86,0.81 ; TP10.1 127.46,2.41
  L4_SIG w0.432: 130.3,3.68 J17.1 ; J17.1 135.69,2.24 ; J17.1 130.3,0.79 ; J17.1 135.69,0.79 ; J17.1 132.99,3.68 ; J17.1 132.99,0.79 ; J17.1 130.3,2.24 ; J17.1 135.69,3.68 ; TP10.1 127.04,3.6 ; TP10.1 124.67,1.23 ; TP10.1 127.46,2.41 ; TP10.1 127.04,1.23 ; TP10.1 124.26,2.41 ; TP10.1 125.86,4.01 ; TP10.1 125.86,0.81 ; TP10.1 124.67,3.6
  L6_SIG w0.432: J17.1 135.69,0.79 ; J17.1 130.3,3.68 ; J17.1 130.3,0.79 ; J17.1 135.69,2.24 ; J17.1 132.99,3.68 ; J17.1 135.69,3.68 ; J17.1 132.99,0.79 ; J17.1 130.3,2.24 ; 125.86,0.81 TP10.1 ; TP10.1 127.04,3.6 ; TP10.1 124.26,2.41 ; TP10.1 127.04,1.23 ; TP10.1 125.86,4.01 ; TP10.1 127.46,2.41 ; TP10.1 124.67,1.23 ; TP10.1 124.67,3.6
  L8_SIG w0.432: 132.99,0.79 J17.1 ; J17.1 130.3,0.79 ; J17.1 130.3,3.68 ; J17.1 132.99,3.68 ; J17.1 135.69,2.24 ; J17.1 130.3,2.24 ; J17.1 135.69,0.79 ; J17.1 135.69,3.68 ; TP10.1 127.04,1.23 ; TP10.1 127.46,2.41 ; TP10.1 124.26,2.41 ; TP10.1 127.04,3.6 ; TP10.1 125.86,0.81 ; TP10.1 124.67,3.6 ; TP10.1 125.86,4.01 ; TP10.1 124.67,1.23
  L10_PWR_SIG w0.432: 130.3,2.24 J17.1 ; J17.1 130.3,0.79 ; J17.1 130.3,3.68 ; J17.1 132.99,3.68 ; J17.1 135.69,0.79 ; J17.1 135.69,2.24 ; J17.1 132.99,0.79 ; J17.1 135.69,3.68 ; TP10.1 125.86,4.01 ; TP10.1 125.86,0.81 ; TP10.1 124.67,1.23 ; TP10.1 127.46,2.41 ; TP10.1 124.26,2.41 ; TP10.1 124.67,3.6 ; TP10.1 127.04,3.6 ; TP10.1 127.04,1.23
  BOTTOM w0.127: v2(132.21,6.46) 132.3,6.55 Q4.8 ; v2(132.21,6.46) v2(131.21,6.46) ; v2(132.21,6.46) v2(132.21,7.46) ; v2(131.19,8.45) 131.19,9.44 v2(131.21,9.46) ; v2(131.19,8.45) 131.18,8.46 v2(130.21,8.46) ; v2(131.19,8.45) 131.21,8.43 v2(131.21,7.46) ; v2(131.19,8.45) 132.2,8.45 v2(132.21,8.46) ; v2(132.21,8.46) v2(132.21,7.46) ; v2(132.21,8.46) v2(132.21,9.46) ; v2(132.21,7.46) v2(131.21,7.46) ; v2(132.21,10.46) 132.3,10.36 Q4.5 ; v2(132.21,10.46) v2(131.21,10.46) ; v2(132.21,10.46) v2(132.21,9.46) ; v2(130.21,9.46) v2(130.21,10.46) v2(131.21,10.46) ; v2(130.21,9.46) v2(130.21,8.46) ; v2(130.21,9.46) v2(131.21,9.46) ; v2(131.21,9.46) v2(132.21,9.46) ; v2(131.21,9.46) v2(131.21,10.46) ; v2(130.21,7.46) v2(130.21,8.46) ; v2(130.21,7.46) v2(131.21,7.46) ; v2(130.21,7.46) v2(130.21,6.46) v2(131.21,6.46) ; v2(131.21,7.46) v2(131.21,6.46)
  BOTTOM w0.432: 130.3,2.24 J17.1 ; J17.1 132.99,3.68 ; J17.1 135.69,3.68 ; J17.1 130.3,0.79 ; J17.1 132.99,0.79 ; J17.1 135.69,0.79 ; J17.1 130.3,3.68 ; J17.1 135.69,2.24 ; TP10.1 125.86,4.01 ; TP10.1 124.26,2.41 ; TP10.1 127.04,3.6 ; TP10.1 124.67,1.23 ; TP10.1 125.86,0.81 ; TP10.1 124.67,3.6 ; TP10.1 127.04,1.23 ; TP10.1 127.46,2.41
  vias: v2(125.86,4.95) v2(127.64,5.08) v2(128.27,3.81) v2(128.27,2.54) v2(128.27,1.27) v2(128.91,5.08) v2(129.54,3.81) v2(129.54,2.54) v2(129.54,1.27) v2(130.18,5.08) v2(131.44,5.08) v2(132.72,5.08)
5VUSB: length 39.8
  L10_PWR_SIG w0.305: v1(106.37,42.64) 106.39,42.64 108.25,40.77 108.25,38.33 111.71,34.87 114.45,34.87 117.3,32.03 127.2,32.03 133.43,25.81 v1(133.43,21.41)
+1.8V_ANA: length 93.8
  L3_PWR_SIG w0.102: v1(15.05,24.87) 14.66,24.47 14.66,20.42 14.33,20.09 14.33,19.7
  L3_PWR_SIG w0.127: v1(87.4,12.52) 87.35,12.52 84.23,9.4 67.84,9.4 67.08,10.16 48.49,10.16 46.02,7.7 38.18,7.7 36.88,6.4 31.04,6.4 30.76,6.68 30.76,10.79 30.28,11.28 20.57,11.28 15.39,16.46 14.86,16.46 14.33,16.99 14.33,19.7
  L3_PWR_SIG w0.305: v1(15.05,25.67) v1(15.05,24.87)
  BOTTOM w0.305: v1(14.25,24.87) 14.16,24.97 C78.1 ; C73.1 14.88,24.7 v1(15.05,24.87) v1(15.05,25.67) 14.87,25.86 C74.1 ; C77.1 14.16,25.58 v1(14.25,25.67)
  vias: v1(12.22,13.76) v1(16.1,9.98) v1(25.04,9.5) v1(25.07,10.62) v1(26.14,9.47) v1(26.16,10.59) v1(27.3,10.59) v1(27.28,9.47) v1(28.52,10.59) v1(28.5,9.47) v1(29.74,9.47) v1(29.77,10.59)
+1.8V_CLK: length 0.5
  BOTTOM w0.305: C103.1 18.1,20.72 v1(18.25,20.87) ; v1(16.65,20.87) 16.67,20.85 C82.1 ; C81.1 15.83,20.85 v1(15.85,20.87)
  vias: v1(26.39,14.63) v1(26.39,13.56) v1(27.53,14.63) v1(27.53,13.56) v1(28.63,14.61) v1(28.63,13.54) v1(29.84,14.61) v1(29.84,13.54) v1(30.99,14.61) v1(30.99,13.54) v1(32.13,14.63) v1(32.13,13.56)
+1.8V_DIG: length 57
  L6_SIG w0.508: JP2.1 83.12,14.57 85.17,12.52 85.17,11.25 88.82,7.59 92,7.59 92.41,8 102.23,8 v1(103.12,8.89)
  L8_SIG w0.508: 58.62,14.48 58.62,13.54 v1(58.72,13.44) ; 58.62,14.48 v1(57.66,14.48) 57.66,13.51 ; 58.62,14.48 57.66,13.51 ; 58.62,14.48 v1(58.8,14.48) ; v1(58.72,13.44) 58.72,14.4 v1(58.8,14.48) ; v1(58.72,13.44) v1(57.58,13.44) 57.66,13.51 ; v1(58.8,14.48) 59.06,14.48
  L8_SIG w0.762: 59.06,14.48 59.66,15.09 78.07,15.09 JP1.1 JP2.1
  BOTTOM w0.305: v1(22.25,25.67) 22.1,25.83 22.1,26.32 v1(22.25,26.47) ; C91.1 21.56,20.76 v1(21.45,20.87)
  vias: v1(19.85,25.67) v1(20.65,20.87) v1(53.01,13.44) v1(53.09,14.48) v1(54.23,14.48) v1(54.15,13.44) v1(55.3,13.44) v1(55.37,14.48) v1(56.44,13.44) v1(56.52,14.48)
+1.8V_VDDVCO: length 3.6
  L10_PWR_SIG w0.102: 16.74,20.35 17.04,20.65 17.04,21.03 16.81,21.26 16.81,21.29 ; 16.13,22.07 15.7,22.07 15.47,21.84 15.47,21.51 15.57,21.41 15.57,21.34 ; 16.81,21.29 17.04,21.51 17.04,21.84 16.81,22.07 16.81,22.1 ; 16.81,21.29 16.66,21.29
  vias: v1(16.65,23.27) v1(16.65,22.47) v1(23.11,14.1) v1(23.11,13.21) v1(24.13,15.11) v1(24.13,14.1) v1(24.13,13.21) v1(25.02,15.11) v1(25.02,14.1) v1(25.02,13.21) v1(57.53,17.27)
+3.3V: length 1.6
  TOP w0.305: 112.9,13.06 112.94,13.01 U23.8
  vias: v1(103.93,34.29) v1(103.91,33.38) v1(105.1,34.26) v1(105.08,33.35) v1(106.32,34.29) v1(106.3,33.38) v1(107.44,33.38) v1(107.46,34.29) v1(111.99,17.09) v1(111.99,15.95) v1(112.01,14.94) v1(111.99,13.73) v1(111.99,12.58) v1(112.93,17.12) v1(112.93,15.98) v1(112.93,14.96) v1(112.9,13.74) v1(112.9,12.6)
+3.3V_LMX: length 5
  TOP w0.254: v3(69.52,51.05) 69.52,50.39 v3(69.55,50.37) ; v3(68.55,44.98) v3(68.55,44.3) ; v3(67.08,50.39) 67.06,50.42 v3(67.06,51.03) ; v3(72.01,46.91) v3(72.67,46.91) ; v3(66.62,45.42) v3(65.96,45.42) ; v1(73.56,44.48) v1(72.67,44.48) ; v3(66.6,47.42) v3(65.94,47.42)
  BOTTOM w0.305: C356.1 104.85,12.75 v1(104.9,12.7)
  vias: v1(72.64,43.51) v1(73.53,43.51) v1(104.9,14.48) v1(104.9,13.59) v1(105.79,14.48) v1(105.79,13.59) v1(105.79,12.7) v1(106.68,14.48) v1(106.68,13.59) v1(106.68,12.7) v1(107.57,14.48) v1(107.57,13.59) v1(107.57,12.7)
+3.3V_LMXRF:
  vias: v1(62.8,50.58) v1(63.24,50.15) v1(64.13,51.91) v1(66.92,52.5) v1(68.8,52.5) v1(77.27,51.26) v1(77.27,49.23) v1(77.27,47.14) v1(78.77,44.37) v1(78.77,42.37) v1(78.77,40.39) v1(80.52,37.47) v1(80.49,33.45) v1(80.59,35.48) v1(107.57,18.41) v1(107.57,17.53) v1(107.57,16.64) v1(108.46,18.41) v1(108.46,17.53) v1(108.46,16.64) v1(109.35,18.41) v1(109.35,17.53) v1(109.35,16.64) v1(110.36,18.41) v1(110.36,17.53) v1(110.36,16.64)
+3.3VCLK: length 92.2
  TOP w0.305: v1(36.02,34.87) 36.02,35.15 v1(36.45,35.59) 37.52,35.59 v1(37.67,35.43)
  TOP w0.508: v1(43.64,37.77) 43.61,37.74 v1(42.77,37.74) ; v1(43.64,36.93) 43.61,36.91 v1(42.77,36.91) 42.88,37.01 42.88,37.72
  L3_PWR_SIG w0.305: 58.14,34.87 59.36,36.09 v1(59.39,36.09) 59.39,38.2 62.56,41.38 63.12,41.38 63.53,40.97 v1(63.53,40.84)
  L3_PWR_SIG w0.432: 49.81,38.07 JP6.2 ; JP6.2 50.08,38.89 ; JP6.2 50.9,36.97 ; JP6.2 51.73,38.89 ; JP6.2 51.99,38.07 ; JP6.2 50.08,37.24
  L6_SIG w0.127: v1(106.83,39.95) 104.78,39.95 103.28,41.45 101.19,41.45 100.71,41.94 96.72,41.94 94.34,44.32 90.58,44.32 88.75,46.15 83.74,46.15 82.98,45.39 79.07,45.39 75.79,42.11 70.21,42.11 69.75,42.57 49.66,42.57 48.31,41.22 46.51,41.22 46.05,40.77 46.05,40.18 v1(43.64,37.77)
  BOTTOM w0.127: U22.3 106.86,39.98 v1(106.83,39.95)
  vias: v1(29.84,36.32) v1(29.84,35.48) v1(30.71,36.35) v1(30.71,35.51) v1(31.14,47.75) v1(32.11,47.75) v1(33.1,47.75) v1(34.09,47.75) v1(35.74,47.75) v1(37.59,47.75) v1(38.46,47.75) v1(40.82,47.04) v1(40.82,46.2) v1(41.68,47.07) v1(41.68,46.23) v1(48.49,36.5) v1(48.49,34.62) v1(98.73,33.6) v1(98.76,32.38) v1(99.85,33.6) v1(99.87,32.38) v1(100.81,33.6) v1(100.84,32.38) v1(101.85,33.63) v1(101.88,32.41) v1(102.77,33.63) v1(102.79,32.41)
+5VIN: length 47.7
  TOP w0.305: U21.12 67.89,8.07 68.38,7.58 68.38,7.37 68.91,6.83 v1(69.06,6.83)
  TOP w0.508: v1(136.96,34.8) 137.92,33.83 D6.1
  L3_PWR_SIG w0.305: 113.16,43.89 113.28,43.76 117.07,43.76 117.68,44.37 120.52,44.37 120.93,43.97 125.35,43.97 125.53,44.15 128.22,44.15 128.7,43.66 132.13,43.66 132.64,44.17 134.67,44.17 v1(137.97,40.87) 136.96,39.85 v1(136.96,34.8)
  L3_PWR_SIG w0.432: J38.1 109.96,34.49 ; J38.1 109.08,34.2 ; J38.1 109.08,32.45 ; J38.1 109.96,32.16 ; J38.1 108.79,33.32
  L3_PWR_SIG w1.016: 108.86,34.65 110.06,33.45 109.68,33.48 110.03,33.25 108.71,31.93
  vias: v1(51.21,3.71) v1(51.21,2.57) v1(51.21,1.55) v1(51.26,4.75) v1(52.22,3.71) v1(52.22,2.57) v1(52.22,1.55) v1(52.27,4.75) v1(92,11.43) v1(92,10.41) v1(92.94,11.43) v1(92.94,10.41) v1(94.08,11.43) v1(94.08,10.41) v1(95.05,11.43) v1(95.05,10.41) v1(101.22,17.53) v1(101.17,16.48) v1(101.17,15.34) v1(101.17,14.33) v1(102.23,17.53) v1(102.18,16.48) v1(102.18,15.34) v1(102.18,14.33) v1(110.49,46.61) v1(110.47,45.68) v1(110.49,44.7) v1(111.38,46.61) v1(111.36,45.68) v1(111.38,44.7) v1(117.73,6.86) v1(117.68,5.82) v1(117.68,4.67) v1(117.68,3.66) v1(118.75,6.86) v1(118.69,5.82) v1(118.69,4.67) v1(118.69,3.66) v1(119.84,6.83) v1(119.84,5.82) v1(119.84,4.67) v1(119.84,3.66) v1(120.98,6.83) v1(120.98,5.82) v1(120.98,4.67) v1(120.98,3.66)
+5VIN_ADC: length 3.4
  BOTTOM w0.127: R332.1 133.3,37.26 132.97,36.93 v1(132.97,35.18)
  vias: v1(117.14,35.08) v1(117.14,33.66) v1(118.16,35.08) v1(118.16,33.66) v1(118.95,16.23) v1(118.97,17.25) v1(118.97,15.16) v1(119.2,35.08) v1(119.2,33.66) v1(120.02,15.29) v1(120.07,17.32) v1(120.07,16.31) v1(120.07,14.27) v1(120.17,35.08) v1(120.17,33.66) v1(121.08,17.32) v1(121.08,16.31) v1(121.11,15.24) v1(121.11,14.22) v1(122.1,17.32) v1(122.1,16.31) v1(122.12,15.24) v1(122.12,14.22) v1(124.51,35.18) v1(124.51,33.76) v1(125.53,35.18) v1(125.53,33.76) v1(126.57,35.18) v1(126.57,33.76) v1(127.53,35.18) v1(127.53,33.76) v1(131.95,35.18) v1(131.95,33.76) v1(132.97,33.76) v1(134.01,35.18) v1(134.01,33.76) v1(134.98,35.18) v1(134.98,33.76)
+5VIN_CLK:
  vias: v1(111.99,36.45) v1(111.99,35.43) v1(112.19,37.39) v1(113,36.45) v1(113,35.43) v1(113.06,38.35) v1(113.06,37.34) v1(114.3,9.22) v1(114.3,8.2) v1(115.32,9.22) v1(115.32,8.2) v1(116.46,9.22) v1(116.46,8.2) v1(117.63,10.16) v1(117.63,9.14) v1(118.64,10.16) v1(118.64,9.14) v1(119.53,10.16) v1(119.53,9.14) v1(120.55,10.16) v1(120.55,9.14) v1(121.56,10.16) v1(121.56,9.14)
-1.8V: length 0.7
  BOTTOM w0.305: 42.67,2.41 U15.4
-1.8V_VEE: length 53.4
  TOP w0.305: v1(15.85,22.47) v1(15.85,23.27) ; v1(15.85,27.27) v1(15.85,28.07)
  L10_PWR_SIG w0.102: 14.5,26.16 14.66,26.31 14.66,26.62 14.58,26.7 14.58,26.72 ; 14.71,26.92 14.83,26.92 14.88,26.87 15.14,26.87 15.16,26.89 15.21,26.89 15.44,27.12 ; 15.52,28.42 15.85,28.09 v1(15.85,28.07) 16.03,28.24 ; 15.54,27.3 15.44,27.2 15.44,27.12 ; 15.44,27.12 15.7,27.12 v1(15.85,27.27) ; 14.35,19.7 14.35,20.14 14.66,20.45 14.66,21.82 14.91,22.07 15.21,22.07 15.61,22.47 v1(15.85,22.47)
  L10_PWR_SIG w0.127: 14.35,19.7 14.35,16.21 18.01,12.55 25.02,12.55 25.83,11.73 26.92,11.73 27.86,10.79 27.86,10.52 28.32,10.06 28.6,10.06 29.29,9.37 29.29,8.1 31.57,5.82 34.14,5.82 34.62,5.33 38.81,5.33 v1(39.83,4.32)
  L10_PWR_SIG w0.305: v1(15.85,23.27) v1(15.85,22.47) ; 15.85,27.28 15.47,27.66 ; 15.85,27.28 v1(15.85,27.27) 15.58,27.27 15.54,27.3 ; 15.85,27.28 v1(15.85,28.07)
  BOTTOM w0.127: R161.2 41.07,7.24 40.23,6.4 40.23,6.38 39.85,5.99 39.85,4.34 v1(39.83,4.32)
  BOTTOM w0.305: C107.1 15.68,28.24 ; 15.68,28.24 15.68,27.5 15.63,27.44 15.68,27.44 v1(15.85,27.27) v1(15.85,28.07) 15.68,28.24 ; v1(15.85,22.47) 15.68,22.3 C109.1 15.8,22.35 15.8,22.96 C108.1 v1(15.85,23.27) v1(15.85,22.47)
  vias: v1(11.89,19.16) v1(14.1,29.97) v1(28.7,3.17) v1(28.65,2.16) v1(29.84,3.17) v1(29.79,2.16) v1(30.94,2.16) v1(30.99,3.17) v1(32.13,3.17) v1(32.08,2.16) v1(33.15,3.17) v1(33.1,2.16)
AVDD1.9V: length 5.6
  TOP w0.254: v3(31.14,60.3) 30.25,60.3 v3(30.23,60.33) ; v3(35.74,64.36) 35.79,64.31 v3(35.79,63.45) ; v3(35.79,53.65) 35.79,52.61 v3(35.79,52.6) ; U2.39 32.79,52.91 v3(32.69,52.81) ; v3(32.79,64.36) 32.79,64.36 v3(32.79,63.45) ; v3(31.14,56.8) 30.33,56.8 v3(30.28,56.74)
  TOP w0.305: C145.1 v3(30.23,60.33)
  vias: v1(115.44,49.78) v1(115.49,48.69) v1(116.46,49.78) v1(116.51,48.69) v1(117.6,49.78) v1(117.65,48.69) v1(118.75,49.78) v1(118.8,48.69) v1(119.76,49.78) v1(119.81,48.69) v3(32.79,53.64)
AVDD1.15V: length 11.5
  TOP w0.254: v3(32.23,64.06) 32.29,64 v3(32.29,63.45) ; v3(33.29,53.65) 33.29,53.28 v3(33.27,53.26) ; v3(34.79,53.65) 34.79,53.28 34.82,53.24 34.82,52.96 v3(35.18,52.6) 35.29,52.72 v3(35.29,53.65) ; v3(32.29,53.65) 32.29,53.22 v3(32.11,53.04) ; v3(36.29,63.45) 36.29,64.31 v3(36.35,64.36) ; v3(31.14,57.3) 30.33,57.3 v3(30.28,57.35) ; v3(34.8,63.42) 34.79,63.43 U2.12 34.8,63.45 v3(34.8,64.08) ; v3(31.14,59.8) 30.33,59.8 v3(30.25,59.72) ; v3(33.29,63.45) 33.29,63.87 v3(33.3,63.88) ; v3(36.29,53.65) 36.29,52.71 v3(36.4,52.6)
  L3_PWR_SIG w0.127: v3(36.35,64.36) 36.35,63.5 v3(36.29,63.45) ; 36.2,52.45 36.35,52.6 v3(36.4,52.6) 36.29,52.71 v3(36.29,53.65)
  BOTTOM w0.254: C115.1 33.29,53.64 v3(33.29,53.65) ; C116.1 32.29,53.64 v3(32.29,53.65)
  vias: v1(128.02,49.53) v1(127.99,48.51) v1(129.29,49.53) v1(129.26,48.51) v1(130.53,48.51) v1(130.56,49.53) v1(131.83,49.53) v1(131.8,48.51) v1(133.22,49.53) v1(133.2,48.51)
DVDD1.15V: length 92
  TOP w0.254: v3(40.94,55.3) 41.78,55.3 v3(41.81,55.27) ; v3(38.79,53.65) 38.79,52.69 v3(38.79,52.68) ; v3(36.96,64.36) 36.79,64.2 v3(36.79,63.45) ; v3(38.79,64.41) 38.79,64.41 v3(38.79,63.45) ; v3(41.78,58.78) 41.76,58.8 v3(40.94,58.8) ; v3(41.78,61.8) 41.78,61.8 v3(40.94,61.8) ; v3(36.79,53.65) 36.79,53.22 37.03,52.98 v3(37.03,52.6)
  L3_PWR_SIG w0.127: v3(36.79,53.65) 36.79,52.84 v3(37.03,52.6) ; v3(36.79,63.45) 36.79,64.2 v3(36.96,64.36)
  L3_PWR_SIG w0.305: 65.25,56.34 65.2,56.29 65.23,56.26 65.23,48.41 64.64,47.83 64.64,39.98 66.81,37.81 JP4.1
  L6_SIG w0.305: 84.73,35 84.18,34.44 79.73,34.44 78.71,33.43 73.25,33.43 72.69,32.87 68.78,32.87 68.07,33.58 68.07,36.68 66.94,37.81 JP4.1 ; 84.73,35 84.73,38.28 v3(85.04,38.58) v3(85.47,38.58) ; 84.73,35 85.27,34.47 v3(86.13,34.47) v3(86.13,34.92)
  BOTTOM w0.305: v1(96.44,6.96) 97.87,8.38 97.87,16.41 95.3,18.97 95.3,20.07 94.36,21.01 94.36,23.9 92.66,25.6 92.66,29.59 91.97,30.28 91.52,30.28 91.08,30.71 91.08,31.17 88.65,33.6 87,33.6 v3(86.13,34.47) v3(86.13,34.92)
  vias: v1(121.67,49.66) v1(121.67,48.64) v1(122.68,49.66) v1(122.68,48.64) v1(123.7,49.66) v1(123.72,48.67) v1(124.84,49.66) v1(124.84,48.64) v1(125.98,49.66) v1(125.98,48.64)
